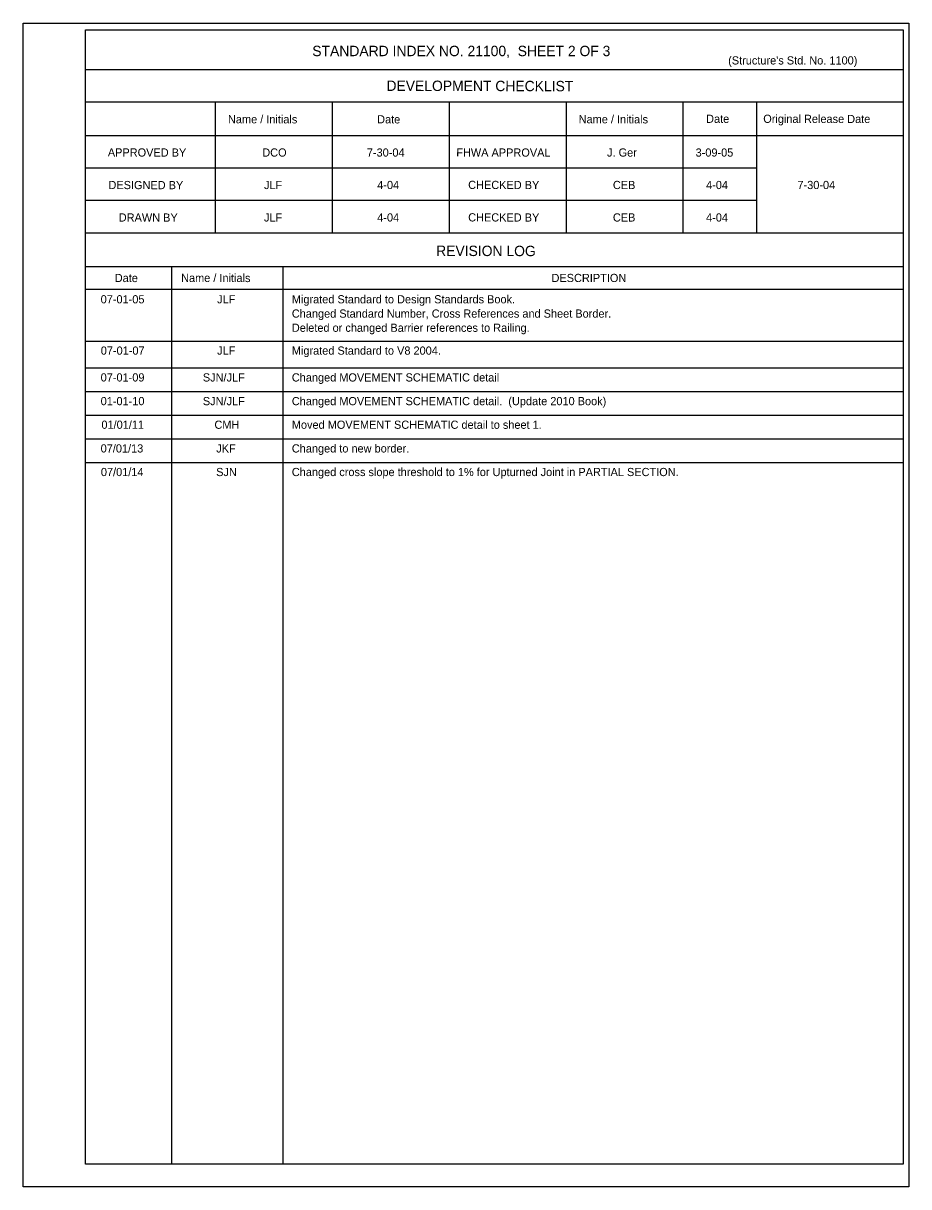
# Model space of a CAD drawing. Extents: x 0 to 26, y -2.5 to 15.3.
# Drawn here: x 17.83 to 26.01, y -0.19 to 10.56 of the extents above; entities that cross this region are included whole.
import ezdxf

# ---------------------------------------------------------------- set-up
doc = ezdxf.new("R2010")
doc.units = 0
for name, color, linetype in [('Border', 7, 'Continuous'), ('Dimension', 7, 'Continuous'), ('PlotBorder_dp', 7, 'Continuous'), ('TextStructures', 7, 'Continuous')]:
    doc.layers.add(name, color=color, linetype=linetype)

msp = doc.modelspace()

# ---------------------------------------------------------------- linework, layer by layer
at = {"layer": 'Border'}
for p, q in [((25.955, 10.132), (18.4, 10.132)), ((25.955, 9.832), (18.4, 9.832)), ((19.6, 9.832), (19.6, 8.622)), ((20.68, 9.832), (20.68, 8.622)), ((21.76, 9.832), (21.76, 8.622)), ((22.84, 9.832), (22.84, 8.622)), ((23.92, 9.832), (23.92, 8.622)), ((24.601, 9.832), (24.601, 8.622)), ((25.955, 9.522), (18.4, 9.522)), ((24.601, 9.222), (18.4, 9.222)), ((24.601, 8.922), (18.4, 8.922)), ((25.955, 8.622), (18.4, 8.622)), ((25.955, 8.311), (18.4, 8.311)), ((19.195, 8.311), (19.195, 0.021)), ((20.223, 8.311), (20.223, 0.021)), ((25.955, 8.1), (18.4, 8.1))]:
    msp.add_line(p, q, dxfattribs=at)
msp.add_lwpolyline([(18.4, 10.5), (25.955, 10.5), (25.955, 0.021), (18.4, 0.021)], close=True, dxfattribs=at)
at = {"layer": 'Dimension'}
for p, q in [((18.4, 7.625), (25.955, 7.625)), ((18.4, 7.378), (25.955, 7.378)), ((18.4, 7.159), (25.955, 7.159)), ((18.4, 6.941), (25.955, 6.941)), ((18.4, 6.722), (25.955, 6.722)), ((18.4, 6.504), (25.955, 6.504))]:
    msp.add_line(p, q, dxfattribs=at)
at = {"layer": 'PlotBorder_dp'}
msp.add_line((17.826, -0.189), (17.826, -0.189), dxfattribs=at)
msp.add_lwpolyline([(17.826, 10.561), (26.006, 10.561), (26.006, -0.189), (17.826, -0.189)], close=True, dxfattribs=at)

# ---------------------------------------------------------------- texts
at = {"layer": 'TextStructures'}
for s, height, p in [('STANDARD INDEX NO. 21100,  SHEET 2 OF 3', 0.096, (20.496, 10.257)), ("(Structure's Std. No. 1100)", 0.0756, (24.338, 10.18)), ('DCO', 0.0756, (20.034, 9.329)), ('7-30-04', 0.0756, (21, 9.329)), ('J. Ger', 0.0756, (23.219, 9.329)), ('3-09-05', 0.0756, (24.037, 9.329)), ('JLF', 0.0756, (20.05, 9.029)), ('4-04', 0.0756, (21.096, 9.029)), ('CEB', 0.0756, (23.273, 9.029)), ('4-04', 0.0756, (24.134, 9.029)), ('7-30-04', 0.0756, (24.978, 9.029)), ('JLF', 0.0756, (20.05, 8.729)), ('4-04', 0.0756, (21.096, 8.729)), ('CEB', 0.0756, (23.273, 8.729)), ('4-04', 0.0756, (24.134, 8.729)), ('DESCRIPTION', 0.0756, (22.706, 8.17)), ('07-01-05', 0.0756, (18.541, 7.973)), ('JLF', 0.0756, (19.617, 7.973)), ('Migrated Standard to Design Standards Book.', 0.0756, (20.307, 7.973)), ('Changed Standard Number, Cross References and Sheet Border.', 0.0756, (20.307, 7.841)), ('Deleted or changed Barrier references to Railing.', 0.0756, (20.307, 7.71)), ('07-01-07', 0.0756, (18.542, 7.499)), ('JLF', 0.0756, (19.617, 7.499)), ('Migrated Standard to V8 2004.', 0.0756, (20.307, 7.499)), ('07-01-09', 0.0756, (18.541, 7.251)), ('SJN/JLF', 0.0756, (19.485, 7.251)), ('Changed MOVEMENT SCHEMATIC detail', 0.0756, (20.307, 7.251)), ('01-01-10', 0.0756, (18.541, 7.032)), ('SJN/JLF', 0.0756, (19.485, 7.032)), ('Changed MOVEMENT SCHEMATIC detail.  (Update 2010 Book)', 0.0756, (20.307, 7.032)), ('01/01/11', 0.0756, (18.548, 6.814)), ('CMH', 0.0756, (19.592, 6.814)), ('Moved MOVEMENT SCHEMATIC detail to sheet 1.', 0.0756, (20.307, 6.814)), ('07/01/13', 0.0756, (18.541, 6.595)), ('JKF', 0.0756, (19.609, 6.595)), ('Changed to new border.', 0.0756, (20.307, 6.595)), ('07/01/14', 0.0756, (18.543, 6.377)), ('SJN', 0.0756, (19.608, 6.377)), ('Changed cross slope threshold to 1% for Upturned Joint in PARTIAL SECTION.', 0.0756, (20.307, 6.377))]:
    msp.add_text(s, height=height, dxfattribs=at).set_placement(p)
for s, height, p in [('DEVELOPMENT CHECKLIST', 0.096, (21.181, 9.936)), ('Name / Initials', 0.0756, (19.717, 9.637)), ('Date', 0.0756, (21.095, 9.636)), ('Name / Initials', 0.0756, (22.957, 9.637)), ('Date', 0.0756, (24.134, 9.641)), ('Original Release Date', 0.0756, (24.662, 9.641)), ('APPROVED BY', 0.0756, (18.607, 9.33)), ('FHWA APPROVAL', 0.0756, (21.826, 9.33)), ('DESIGNED BY', 0.0756, (18.613, 9.029)), ('CHECKED BY', 0.0756, (21.936, 9.03)), ('DRAWN BY', 0.0756, (18.708, 8.729)), ('CHECKED BY', 0.0756, (21.936, 8.73)), ('REVISION LOG', 0.096, (21.64, 8.411)), ('Date', 0.0756, (18.671, 8.17)), ('Name / Initials', 0.0756, (19.284, 8.171))]:
    msp.add_text(s, height=height, rotation=359.8756, dxfattribs=at).set_placement(p)

doc.saveas('drawing.dxf')
